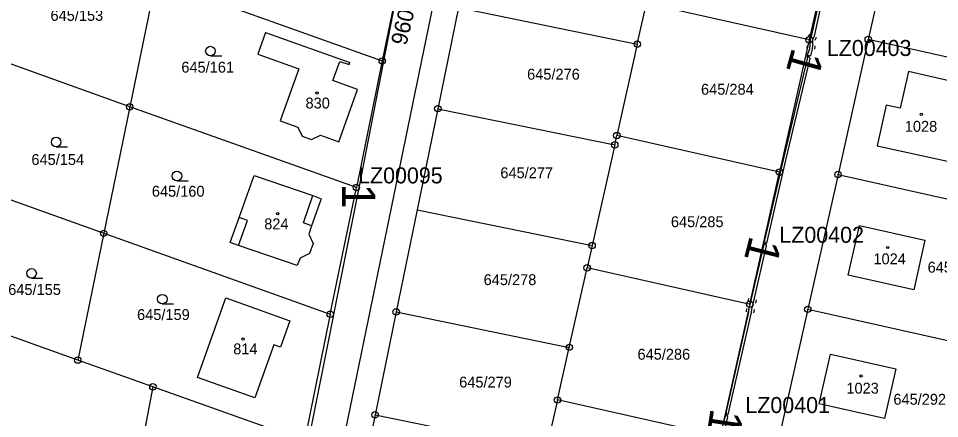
# Model space of a CAD drawing. Extents: x -738131 to -734179, y -1033447 to -1030078.
# Drawn here: x -735885.2 to -735741.5, y -1032929.6 to -1032867.1 of the extents above; entities that cross this region are included whole.
import ezdxf

# ---------------------------------------------------------------- set-up
doc = ezdxf.new("R2010")
doc.units = 0
for name, color, linetype in [('ftf_2010', 7, 'Continuous'), ('ftf_2140', 7, 'Continuous'), ('ftf_3010', 7, 'Continuous'), ('ftf_3010_ftf_3010_gtda_3015_gtda_3015_1', 7, 'Continuous'), ('ftf_3210', 7, 'Continuous'), ('Vrstva 1', 7, 'Continuous'), ('Vrstva 2', 7, 'Continuous'), ('Vrstva 3', 7, 'Continuous'), ('Vrstva 4', 7, 'Continuous'), ('Vrstva 5', 7, 'Continuous'), ('Vrstva 8', 7, 'Continuous')]:
    doc.layers.add(name, color=color, linetype=linetype)

msp = doc.modelspace()

# ---------------------------------------------------------------- linework, layer by layer
at = {"layer": 'ftf_2010'}
for points in [[(-735762.13, -1032872.86), (-735761.6, -1032872.99), (-735761.34, -1032871.9), (-735761.3, -1032871.42), (-735761.26, -1032870.37), (-735761.04, -1032869.89), (-735756.48, -1032849.16), (-735756.03, -1032849.04), (-735749.31, -1032850.8), (-735748.55, -1032850.74), (-735744.57, -1032846.33), (-735738.79, -1032847.35)], [(-735824.95, -1032856.66), (-735832.11, -1032893.62)], [(-735768.71, -1032902.2), (-735768.44, -1032902.26), (-735765.48, -1032889.3), (-735761.69, -1032873.38), (-735762.13, -1032872.86)], [(-735832.11, -1032893.62), (-735840.01, -1032933.23)], [(-735774.72, -1032928.94), (-735774.46, -1032929), (-735770.86, -1032913.07), (-735770.79, -1032912.58), (-735770.55, -1032911.53), (-735770.45, -1032911.03), (-735768.53, -1032902.65), (-735768.71, -1032902.2)], [(-735780.57, -1032954.97), (-735780.26, -1032955.04), (-735779.66, -1032952.3), (-735775.55, -1032933.63), (-735775.37, -1032932.82), (-735774.55, -1032929.39), (-735774.72, -1032928.94)]]:
    msp.add_lwpolyline(points, dxfattribs=at)
at = {"layer": 'ftf_2140'}
for points in [[(-735762.04, -1032872.47), (-735762.13, -1032872.86), (-735761.74, -1032871.84), (-735761.7, -1032871.39), (-735761.65, -1032870.28), (-735761.42, -1032869.76), (-735756.82, -1032848.83), (-735756.03, -1032848.63), (-735749.27, -1032850.39), (-735748.74, -1032850.35), (-735744.72, -1032845.9), (-735738.68, -1032846.96), (-735737.55, -1032847.47), (-735724.37, -1032858.43), (-735723.53, -1032858.96), (-735723.13, -1032859.25), (-735722.7, -1032859.55), (-735714.65, -1032866.02), (-735705.66, -1032873.4), (-735700.66, -1032866.99), (-735699.97, -1032865.87)], [(-735768.71, -1032902.2), (-735768.74, -1032901.78), (-735765.87, -1032889.21), (-735762.13, -1032873.48), (-735762.13, -1032872.86)], [(-735774.72, -1032928.94), (-735774.76, -1032928.52), (-735771.26, -1032913), (-735771.19, -1032912.51), (-735770.94, -1032911.45), (-735770.85, -1032910.95), (-735768.94, -1032902.68), (-735768.71, -1032902.2)], [(-735780.57, -1032954.97), (-735780.56, -1032954.56), (-735780.05, -1032952.22), (-735775.94, -1032933.54), (-735775.76, -1032932.73), (-735774.97, -1032929.42), (-735774.72, -1032928.94)]]:
    msp.add_lwpolyline(points, dxfattribs=at)
at = {"layer": 'ftf_3210'}
for p, q in [((-735761.99, -1032870.05), (-735761.77, -1032869.56)), ((-735760.89, -1032870.53), (-735760.68, -1032870.05)), ((-735762.14, -1032871.83), (-735762.1, -1032871.35)), ((-735760.94, -1032871.93), (-735760.9, -1032871.45)), ((-735771.34, -1032911.38), (-735771.24, -1032910.88)), ((-735770.16, -1032911.61), (-735770.06, -1032911.1)), ((-735771.65, -1032912.97), (-735771.59, -1032912.47)), ((-735770.47, -1032913.13), (-735770.4, -1032912.63))]:
    msp.add_line(p, q, dxfattribs=at)
at = {"layer": 'Vrstva 1'}
for points in [[(-735757.22, -1032849.85), (-735761.85, -1032870.48)], [(-735748.3, -1032851.15), (-735752.63, -1032870.43)], [(-735842.08, -1032970.02), (-735818.34, -1032854.44)], [(-735825.51, -1032859.38), (-735828.45, -1032873.79)], [(-735863.78, -1032861.12), (-735867.85, -1032880.96)], [(-735863.78, -1032861.12), (-735828.45, -1032873.79)], [(-735816.55, -1032865.45), (-735819.78, -1032881.24)], [(-735816.55, -1032865.45), (-735788.66, -1032871.16)], [(-735788.66, -1032871.16), (-735787.22, -1032864.79)], [(-735761.85, -1032870.48), (-735787.22, -1032864.79)], [(-735867.85, -1032880.96), (-735903.15, -1032868.27)], [(-735846.65, -1032869.34), (-735847.88, -1032872.74)], [(-735846.65, -1032869.34), (-735833.52, -1032874.03)], [(-735788.66, -1032871.16), (-735791.85, -1032885.44)], [(-735761.85, -1032870.48), (-735766.49, -1032891.14)], [(-735752.63, -1032870.43), (-735757.35, -1032891.51)], [(-735727.75, -1032876), (-735752.63, -1032870.43)], [(-735847.88, -1032872.74), (-735841.46, -1032875.04)], [(-735836.15, -1032876.83), (-735835.06, -1032873.86)], [(-735835.06, -1032873.86), (-735833.62, -1032874.36)], [(-735833.62, -1032874.36), (-735833.52, -1032874.03)], [(-735828.45, -1032873.79), (-735832.49, -1032893.55)], [(-735841.46, -1032875.04), (-735844.36, -1032883.15)], [(-735746.35, -1032875.45), (-735747.63, -1032881.17)], [(-735740.01, -1032876.87), (-735746.35, -1032875.45)], [(-735832.3, -1032878.23), (-735836.15, -1032876.83)], [(-735835.24, -1032886.4), (-735832.3, -1032878.23)], [(-735867.85, -1032880.96), (-735871.9, -1032900.71)], [(-735832.49, -1032893.55), (-735867.85, -1032880.96)], [(-735819.78, -1032881.24), (-735823.02, -1032897.04)], [(-735819.78, -1032881.24), (-735792.18, -1032886.89)], [(-735749.83, -1032880.68), (-735751.22, -1032887.02)], [(-735747.63, -1032881.17), (-735749.83, -1032880.68)], [(-735844.36, -1032883.15), (-735841.61, -1032884.14)], [(-735841.61, -1032884.14), (-735840.96, -1032885.51)], [(-735840.96, -1032885.51), (-735839.5, -1032886.06)], [(-735839.5, -1032886.06), (-735838.07, -1032885.4)], [(-735838.07, -1032885.4), (-735835.24, -1032886.4)], [(-735792.18, -1032886.89), (-735791.85, -1032885.44)], [(-735766.49, -1032891.14), (-735791.85, -1032885.44)], [(-735792.18, -1032886.89), (-735795.71, -1032902.62)], [(-735751.22, -1032887.02), (-735740.27, -1032889.46)], [(-735907.19, -1032888.04), (-735871.9, -1032900.71)], [(-735850.77, -1032898.25), (-735848.44, -1032891.67)], [(-735848.44, -1032891.67), (-735839.29, -1032894.81)], [(-735771.06, -1032911.57), (-735766.49, -1032891.14)], [(-735757.35, -1032891.51), (-735762.07, -1032912.58)], [(-735757.35, -1032891.51), (-735732.48, -1032897.08)], [(-735836.56, -1032913.35), (-735832.49, -1032893.55)], [(-735837.99, -1032895.31), (-735839.5, -1032899.53)], [(-735839.29, -1032894.81), (-735837.99, -1032895.31)], [(-735823.02, -1032897.04), (-735826.28, -1032912.99)], [(-735823.02, -1032897.04), (-735795.71, -1032902.62)], [(-735852.17, -1032902.15), (-735850.77, -1032898.25)], [(-735839.5, -1032899.53), (-735839.89, -1032900.83)], [(-735755.75, -1032907.24), (-735754, -1032899.47)], [(-735754, -1032899.47), (-735743.79, -1032901.76)], [(-735871.9, -1032900.71), (-735875.95, -1032920.51)], [(-735871.9, -1032900.71), (-735836.56, -1032913.35)], [(-735839.89, -1032900.83), (-735839.23, -1032902.3)], [(-735743.79, -1032901.76), (-735745.54, -1032909.54)], [(-735850.88, -1032902.6), (-735852.17, -1032902.15)], [(-735841.71, -1032905.76), (-735850.88, -1032902.6)], [(-735839.23, -1032902.3), (-735839.81, -1032903.87)], [(-735795.71, -1032902.62), (-735796.48, -1032906.1)], [(-735841.28, -1032904.59), (-735841.71, -1032905.76)], [(-735839.81, -1032903.87), (-735841.28, -1032904.59)], [(-735799.27, -1032918.52), (-735796.48, -1032906.1)], [(-735771.52, -1032911.7), (-735796.48, -1032906.1)], [(-735745.54, -1032909.54), (-735755.75, -1032907.24)], [(-735857.29, -1032923.22), (-735852.84, -1032910.79)], [(-735852.84, -1032910.79), (-735842.87, -1032914.36)], [(-735771.11, -1032911.79), (-735775.73, -1032932.43)], [(-735771.11, -1032911.79), (-735771.52, -1032911.7)], [(-735771.11, -1032911.79), (-735771.06, -1032911.57)], [(-735826.28, -1032912.99), (-735829.57, -1032929.06)], [(-735826.28, -1032912.99), (-735799.27, -1032918.52)], [(-735762.07, -1032912.58), (-735766.8, -1032933.66)], [(-735762.07, -1032912.58), (-735737.21, -1032918.15)], [(-735842.87, -1032914.36), (-735844.33, -1032918.5)], [(-735836.56, -1032913.35), (-735840.58, -1032933.14)], [(-735875.95, -1032920.51), (-735887.69, -1032916.33)], [(-735845.36, -1032918.14), (-735848.32, -1032926.43)], [(-735844.33, -1032918.5), (-735845.36, -1032918.14)], [(-735801.11, -1032926.74), (-735799.27, -1032918.52)], [(-735760.29, -1032927.32), (-735758.53, -1032919.56)], [(-735758.53, -1032919.56), (-735748.32, -1032921.86)], [(-735864.23, -1032924.69), (-735875.95, -1032920.51)], [(-735748.32, -1032921.86), (-735750.08, -1032929.63)], [(-735848.32, -1032926.43), (-735857.29, -1032923.22)], [(-735864.23, -1032924.69), (-735865.69, -1032932.34)], [(-735840.58, -1032933.14), (-735864.23, -1032924.69)], [(-735801.11, -1032926.74), (-735802.87, -1032934.54)], [(-735775.73, -1032932.43), (-735801.11, -1032926.74)], [(-735750.08, -1032929.63), (-735760.29, -1032927.32)], [(-735829.57, -1032929.06), (-735833, -1032945.82)], [(-735829.57, -1032929.06), (-735802.87, -1032934.54)]]:
    msp.add_lwpolyline(points, dxfattribs=at)
at = {"layer": 'Vrstva 3'}
for p, q in [((-735855.25, -1032873), (-735853.5, -1032873)), ((-735879.32, -1032887.2), (-735877.57, -1032887.2)), ((-735860.48, -1032892.51), (-735858.73, -1032892.51)), ((-735883.16, -1032907.72), (-735881.41, -1032907.72)), ((-735862.76, -1032911.74), (-735861.01, -1032911.74))]:
    msp.add_line(p, q, dxfattribs=at)
for centre in [(-735855.25, -1032872.25), (-735879.32, -1032886.45), (-735860.48, -1032891.76), (-735883.16, -1032906.97), (-735862.76, -1032910.99)]:
    msp.add_circle(centre, 0.75, dxfattribs=at)
at = {"layer": 'Vrstva 4'}
for points in [[(-735840.76, -1032899.06), (-735839.29, -1032894.81)], [(-735850.88, -1032902.6), (-735849.45, -1032898.72)], [(-735849.45, -1032898.72), (-735850.77, -1032898.25)], [(-735839.5, -1032899.53), (-735840.76, -1032899.06)]]:
    msp.add_lwpolyline(points, dxfattribs=at)
at = {"layer": 'Vrstva 5'}
for centre in [(-735838.62, -1032878.81), (-735744.36, -1032882.13), (-735844.75, -1032897.65), (-735749.59, -1032902.92), (-735850.16, -1032917.22), (-735753.76, -1032922.98)]:
    msp.add_circle(centre, 0.175, dxfattribs=at)
at = {"layer": 'Vrstva 8'}
for centre, radius in [((-735761.85, -1032870.48), 0.5), ((-735752.63, -1032870.43), 0.5), ((-735788.66, -1032871.16), 0.5), ((-735788.66, -1032871.16), 0.0303), ((-735761.85, -1032870.48), 0.0303), ((-735752.63, -1032870.43), 0.0303), ((-735828.45, -1032873.79), 0.5), ((-735828.45, -1032873.79), 0.0303), ((-735867.85, -1032880.96), 0.5), ((-735867.85, -1032880.96), 0.0303), ((-735819.78, -1032881.24), 0.5), ((-735819.78, -1032881.24), 0.0303), ((-735791.85, -1032885.44), 0.5), ((-735791.85, -1032885.44), 0.0303), ((-735792.18, -1032886.89), 0.5), ((-735792.18, -1032886.89), 0.0303), ((-735766.49, -1032891.14), 0.5), ((-735766.49, -1032891.14), 0.0303), ((-735757.35, -1032891.51), 0.5), ((-735757.35, -1032891.51), 0.0303), ((-735832.49, -1032893.55), 0.5), ((-735832.49, -1032893.55), 0.0303), ((-735871.9, -1032900.71), 0.5), ((-735871.9, -1032900.71), 0.0303), ((-735795.71, -1032902.62), 0.5), ((-735795.71, -1032902.62), 0.0303), ((-735796.48, -1032906.1), 0.5), ((-735796.48, -1032906.1), 0.0303), ((-735771.11, -1032911.79), 0.5), ((-735771.11, -1032911.79), 0.0303), ((-735836.56, -1032913.35), 0.5), ((-735826.28, -1032912.99), 0.5), ((-735826.28, -1032912.99), 0.0303), ((-735762.07, -1032912.58), 0.5), ((-735762.07, -1032912.58), 0.0303), ((-735836.56, -1032913.35), 0.0303), ((-735799.27, -1032918.52), 0.5), ((-735799.27, -1032918.52), 0.0303), ((-735875.95, -1032920.51), 0.5), ((-735875.95, -1032920.51), 0.0303), ((-735864.23, -1032924.69), 0.5), ((-735864.23, -1032924.69), 0.0303), ((-735801.11, -1032926.74), 0.5), ((-735801.11, -1032926.74), 0.0303), ((-735829.57, -1032929.06), 0.5), ((-735829.57, -1032929.06), 0.0303)]:
    msp.add_circle(centre, radius, dxfattribs=at)

# ---------------------------------------------------------------- texts
at = {"layer": 'ftf_3010'}
for rotation, p in [(254.3302, (-735764.46, -1032871.54)), (270, (-735834.71, -1032892.97)), (255.5744, (-735771.07, -1032900.92)), (261.4521, (-735777.2, -1032927.91))]:
    msp.add_text('1', height=5.2, rotation=rotation, dxfattribs=at).set_placement(p)
at = {"layer": 'ftf_3010_ftf_3010_gtda_3015_gtda_3015_1'}
for s, rotation, p in [('LZ00096', 256.7296, (-735824.1, -1032858.06)), ('LZ00095', 0, (-735832.22, -1032892.91))]:
    msp.add_text(s, height=2.5, rotation=rotation, dxfattribs=at).set_placement(p)
for s, p in [('LZ00403', (-735759.09, -1032873.01)), ('LZ00402', (-735766.5, -1032902.19)), ('LZ00401', (-735771.8, -1032928.78))]:
    msp.add_text(s, height=2.5, dxfattribs=at).set_placement(p)
at = {"layer": 'Vrstva 2'}
for s, p in [('645/153', (-735880.2, -1032867.52)), ('645/161', (-735859.79, -1032875.61)), ('645/276', (-735805.85, -1032876.71)), ('645/284', (-735778.72, -1032879.06)), ('830', (-735840.42, -1032881.21)), ('1028', (-735746.93, -1032884.85)), ('645/154', (-735883.18, -1032890.03)), ('645/277', (-735810.02, -1032892.1)), ('645/160', (-735864.39, -1032894.99)), ('824', (-735846.86, -1032900.09)), ('645/285', (-735783.42, -1032899.75)), ('1024', (-735751.82, -1032905.55)), ('645/291', (-735743.37, -1032906.85)), ('645/278', (-735812.63, -1032908.8)), ('645/155', (-735886.8, -1032910.34)), ('645/159', (-735866.7, -1032914.25)), ('814', (-735851.7, -1032919.61)), ('645/286', (-735788.63, -1032920.45)), ('645/279', (-735816.45, -1032924.8)), ('1023', (-735756.04, -1032925.75)), ('645/292', (-735748.71, -1032927.48))]:
    msp.add_text(s, height=1.7, dxfattribs=at).set_placement(p)

doc.saveas('drawing.dxf')
